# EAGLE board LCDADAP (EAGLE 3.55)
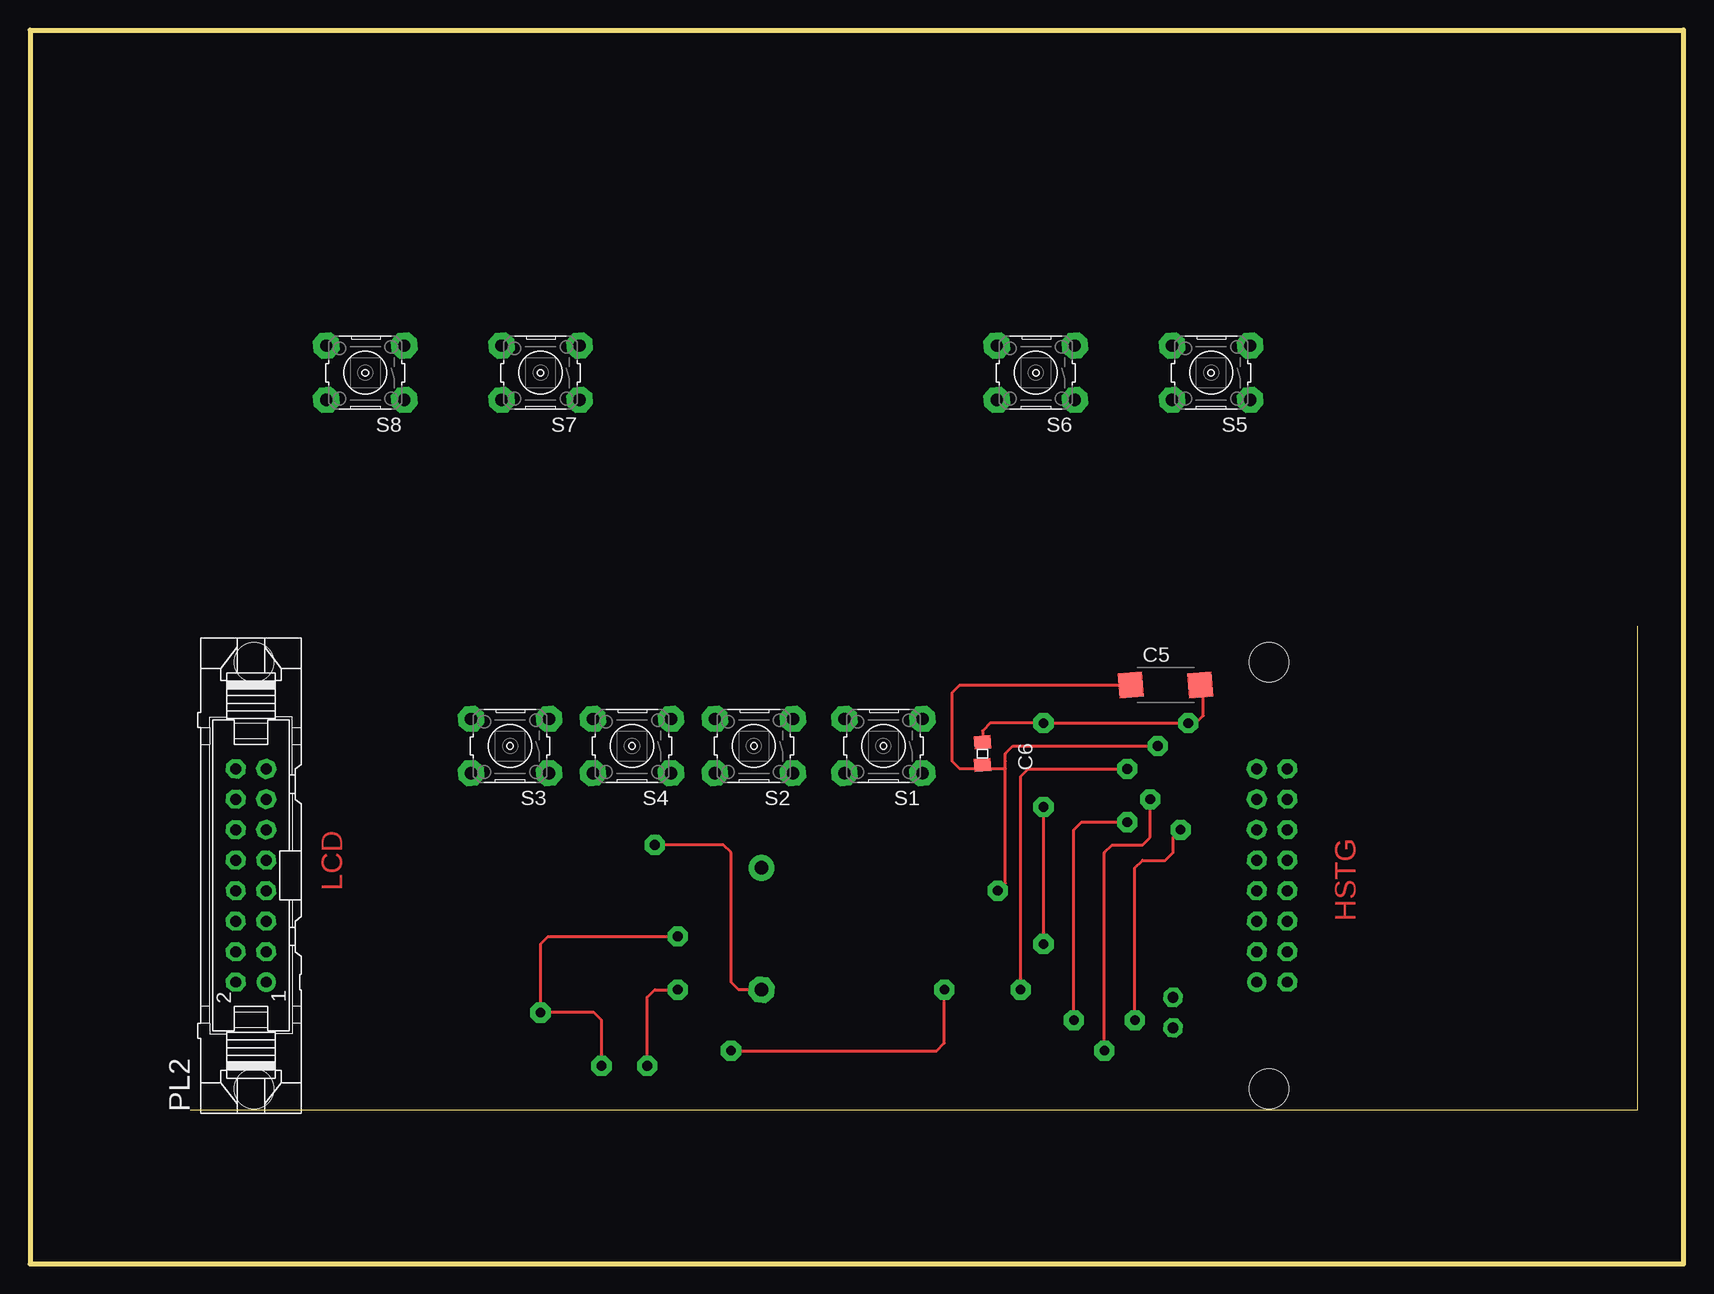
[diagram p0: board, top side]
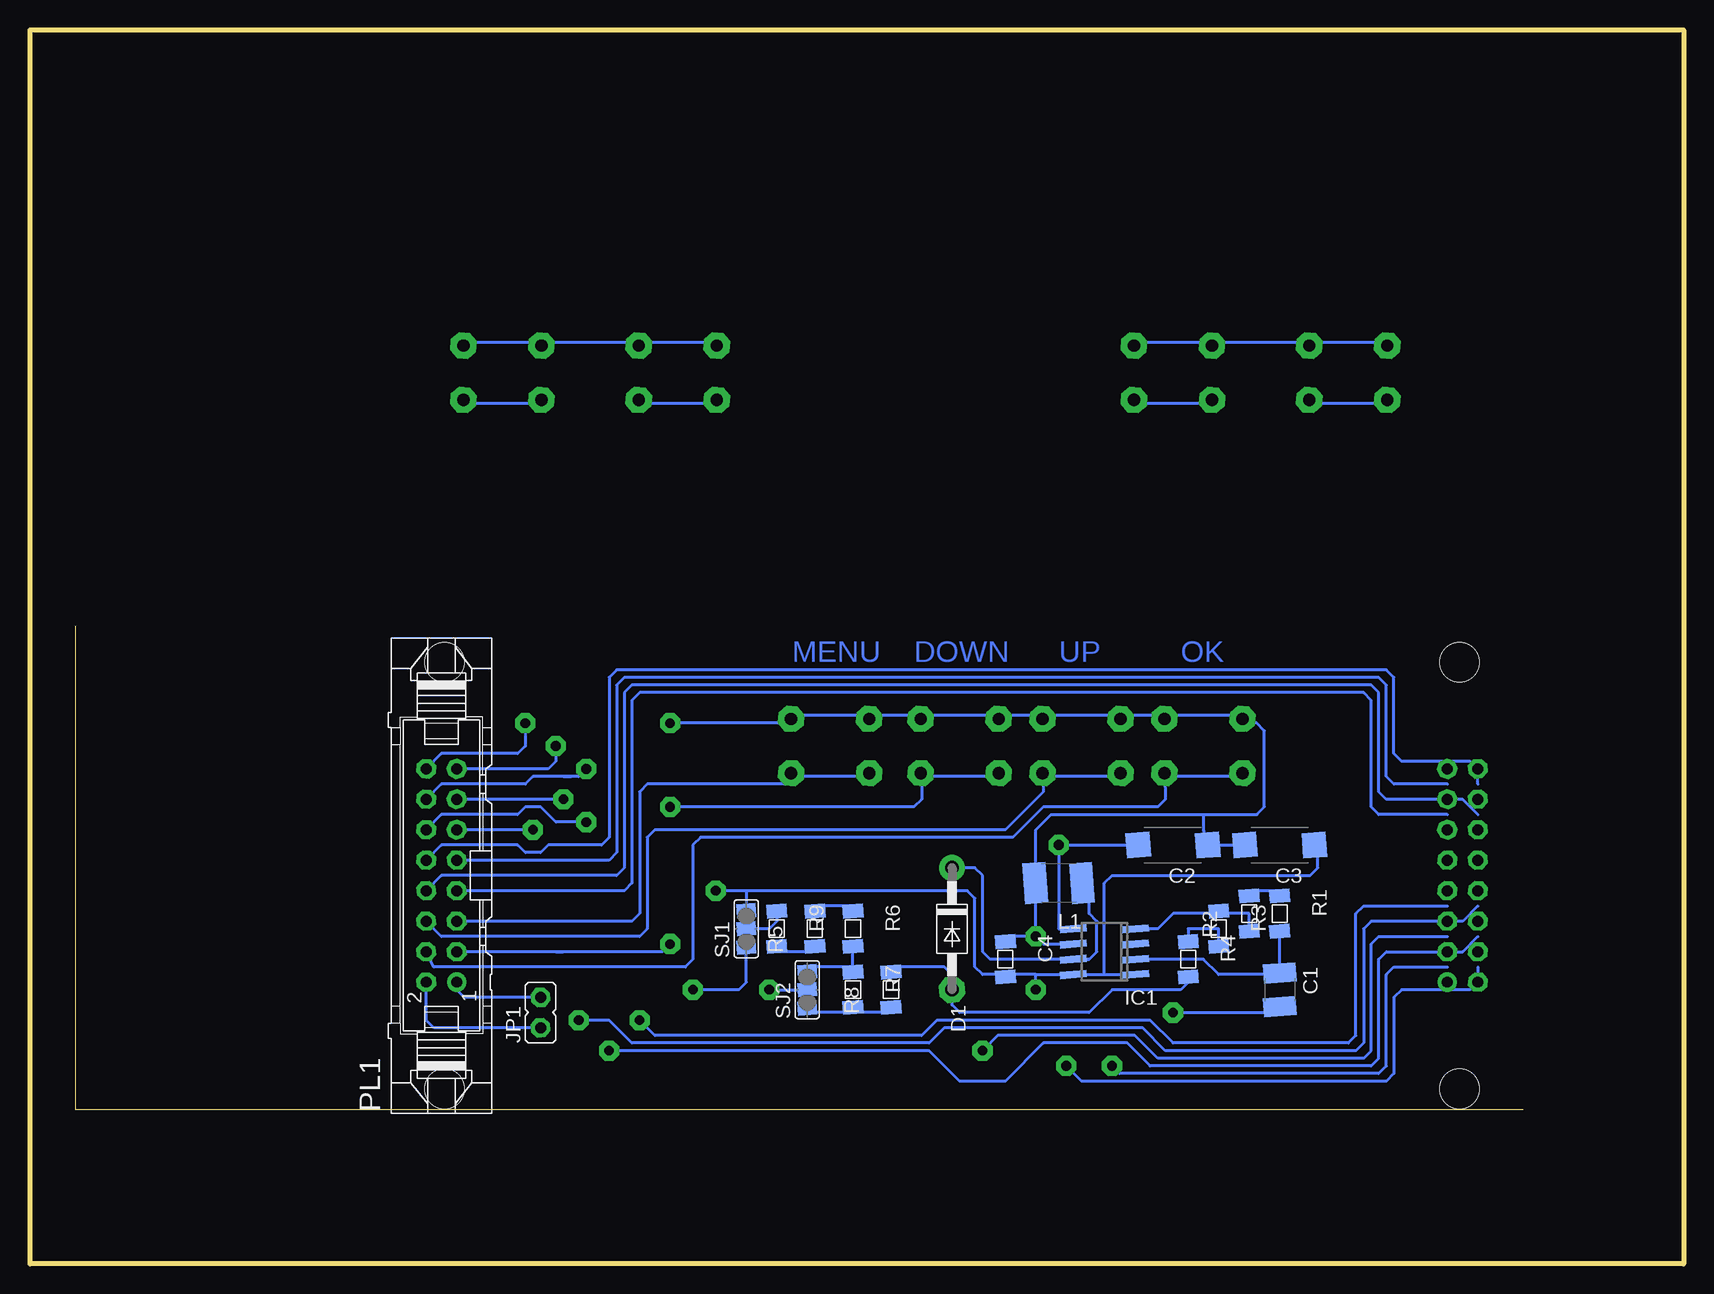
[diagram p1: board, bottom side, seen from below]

Size 137.79 x 102.87 mm. Coordinates in mm from the lower left corner, seen from the top.
Outline: 133.98,53.17 133.98,12.86 13.34,12.86
Outline: 0,0 137.79,0 137.79,102.87 0,102.87 0,0
Copper layers used: Top, Bottom
vRestrict: area 67.3,50.8 to 91.4,74.9

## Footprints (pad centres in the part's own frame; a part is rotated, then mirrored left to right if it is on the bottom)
210 = smd 1.6 x 2.7 rotated 4.3:  -1.4,0 | smd 1.6 x 2.7 rotated 4.4:  1.4,0
512W = smd 2 x 2.1 rotated 4.3:  -2.896,0 | smd 2 x 2.1 rotated 4.4:  2.896,0
06 = smd 1.143 x 1.702 rotated 4.4:  1.473,0 | smd 1.143 x 1.702 rotated 4.3:  -1.473,0
05 = smd 1.092 x 1.397 rotated 4.4:  0.94,0 | smd 1.092 x 1.397 rotated 4.3:  -0.94,0
41-10 = drill 1.118 pad 2.159 octagon:  5.08,0 | drill 1.118 pad 2.159 round:  -5.08,0
8 = smd 0.6 x 2.2 rotated 4.4:  -0.635,-2.6 | smd 0.6 x 2.2 rotated 4.8:  -0.635,2.6 | smd 0.6 x 2.2 rotated 4.3:  -1.905,-2.6 | smd 0.6 x 2.2 rotated 4.5:  0.635,-2.6 | smd 0.6 x 2.2 rotated 4.6:  1.905,-2.6 | smd 0.6 x 2.2 rotated 4.9:  -1.905,2.6 | smd 0.6 x 2.2 rotated 4.7:  0.635,2.6;  1.905,2.6
1 = drill 0.914 pad 1.6 octagon:  0,-1.27;  0,1.27
812 = smd 1.9 x 3.4 rotated 4.3:  -1.95,0 | smd 1.9 x 3.4 rotated 4.4:  1.95,0
V = drill 0.914 pad 1.6 round:  -8.89,-1.27 | drill 0.914 pad 1.6 octagon:  -8.89,1.27;  -6.35,-1.27;  -6.35,1.27;  -3.81,-1.27;  -3.81,1.27;  -1.27,-1.27;  -1.27,1.27;  1.27,-1.27;  1.27,1.27;  3.81,-1.27;  3.81,1.27;  6.35,-1.27;  6.35,1.27;  8.89,-1.27;  8.89,1.27 | hole 3.302: 17.78,-0.254; -17.78,-0.254
F-10XX = drill 1.016 pad 2.159 octagon:  -3.251,2.261;  -3.251,-2.261;  3.251,2.261;  3.251,-2.261
2 = smd 1.168 x 1.6 rotated 4.3:  -1.524,0 | smd 1.168 x 1.6 rotated 4.4:  0,0 | smd 1.168 x 1.6 rotated 4.5:  1.524,0

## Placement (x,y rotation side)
C1  10uF  [210]  33.66,22.86 270 bottom
C2  100uF  [512W]  42.55,34.92 180 bottom
C3  47uF  [512W]  33.66,34.92 180 bottom
C4  1uFceram  [06]  56.52,25.4 270 bottom
C5  100uF  [512W]  94.62,48.26 0 top
C6  100n  [05]  79.38,42.55 270 top
D1  1N5817  [41-10]  60.96,27.94 270 bottom
IC1  MAX755  [8]  48.26,26.04 90 bottom
JP1  JP1E  [1]  95.25,20.95 0 bottom
L1  10uH  [812]  52.07,31.75 180 bottom
PL1  16V  [V]  103.5,32.38 90 bottom
PL2  14V  [V]  18.41,32.38 90 top
R1  2k7  [06]  33.66,29.21 270 bottom
R2  10k  [06]  36.2,29.21 90 bottom
R3  47k  [06]  38.73,27.94 270 bottom
R4  4k7  [06]  41.28,25.4 270 bottom
R5  tbd  [06]  72.39,27.94 90 bottom
R6  tbd  [06]  69.22,27.94 270 bottom
R7  tbd  [06]  69.22,22.86 270 bottom
R8  tbd  [06]  66.04,22.86 90 bottom
R9  tbd  [06]  75.56,27.94 270 bottom
S1  MENU  [F-10XX]  71.12,43.18 180 top
S2  DOWN  [F-10XX]  60.33,43.18 180 top
S3  OK  [F-10XX]  40.01,43.18 180 top
S4  UP  [F-10XX]  50.16,43.18 180 top
S5  menu  [F-10XX]  98.43,74.3 180 top
S6  ok  [F-10XX]  83.82,74.3 180 top
S7  up  [F-10XX]  42.55,74.3 180 top
S8  down  [F-10XX]  27.94,74.3 180 top
SJ1  SJ2  [2]  78.1,27.94 90 bottom
SJ2  SJ2  [2]  73.03,22.86 90 bottom

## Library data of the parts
C1-C3 C5 L1 = ipc-rcl
C4 C6 R1-R9 = smd
D1 = diode
IC1 = andit4at
JP1 = jumps
PL1 PL2 = pinh-v
S1-S8 = keyomron
SJ1 SJ2 = jumper

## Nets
GND: C1. C2. C3. C4. C5. C6. IC1. L1. PL1. PL2. S1. S2. S3. S4.
N$1: IC1. R2. R3.
N$2: C3. C4. C5. C6. IC1. PL1. PL2. SJ1.
N$3: PL1. SJ1.
N$4: PL1. PL2.
N$5: PL1. PL2.
N$6: PL1. PL2.
N$7: PL1. PL2.
N$9: PL1. PL2.
N$10: PL1. PL2.
N$11: PL1. PL2.
N$12: PL1. S4.
N$13: PL1. S1.
N$15: PL1. S2.
N$16: PL1. S3.
N$17: JP1. PL1.
N$18: JP1. PL1.
N$19: PL2. SJ2.
N$20: C2. D1. IC1. R4. R8.
N$21: R1. R2.
N$22: R5. R6.
N$23: R6. R7. SJ2.
N$24: C1. IC1. R1.
N$25: R3. R4.
N$26: R7. R8. SJ2.
N$27: R9. SJ1.
N$28: D1. IC1. L1.
N$29: R5. R9.
N$30: S7. S8.
N$32: S8.
N$33: S7.
N$34: S5. S6.
N$36: S6.
N$37: S5.

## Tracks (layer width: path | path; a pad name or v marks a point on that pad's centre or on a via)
GND  (via drill 0.81 pad 1.68)
  Top 0.254: v47.62,16.51 47.62,20.32 46.99,20.95 v42.55,20.95 42.55,26.67 43.18,27.3 v53.98,27.3 | C6. 79.38,44.45 80.01,45.08 v84.46,45.08 v96.52,45.08 97.16,45.08 97.79,45.72 97.79,48.26 C5.
  Bottom 0.254: 19.69,24.77 24.13,24.77 24.77,24.13 24.77,16.51 25.4,15.88 46.99,15.88 v47.62,16.51 | PL1. 103.5,42.55 97.16,42.55 96.52,43.18 v96.52,45.08 | 40.01,37.47 40.01,36.2 39.65,34.92 C3. | 43.18,45.72 37.47,45.72 S3. 36.83,45.08 35.56,45.08 34.92,44.45 34.92,38.1 35.56,37.47 40.01,37.47 | 43.18,45.72 43.26,45.44 | 43.18,45.72 46.99,45.72 | 46.99,45.72 S4. | 46.99,45.72 53.34,45.72 | 53.34,45.72 53.42,45.44 | 53.34,45.72 57.15,45.72 | 57.15,45.72 S2. | 57.15,45.72 63.5,45.72 | 63.5,45.72 63.58,45.44 | 63.5,45.72 67.94,45.72 | 67.94,45.72 S1. | 67.94,45.72 74.3,45.72 | 74.3,45.72 74.37,45.44 | 74.3,45.72 74.93,45.08 v84.46,45.08 | 53.98,31.75 53.98,36.2 52.7,37.47 40.01,37.47 | 53.98,31.75 L1. | 50.86,26.67 53.34,26.67 v53.98,27.3 | v42.55,20.95 34.29,20.95 33.66,21.59 C1. | C4. 56.52,27.3 v53.98,27.3 | v53.98,27.3 53.98,31.75
N$1
  Bottom 0.254: 45.66,27.94 43.81,27.94 42.55,29.21 38.73,29.21 | R2. 36.2,29.21 38.73,29.21 | 38.73,29.21 R3.
N$2  (via drill 0.81 pad 1.68)
  Top 0.254: v51.44,16.51 51.44,22.23 52.07,22.86 v53.98,22.86 | v93.98,43.18 81.91,43.18 81.28,42.55 81.28,41.91 81.28,41.27 | v80.65,31.11 81.28,31.75 81.28,41.27 | 91.72,48.26 77.47,48.26 76.84,47.62 76.84,41.91 77.47,41.27 79.38,41.27 | 79.38,41.27 79.38,41.61 | 81.28,41.27 79.38,41.27
  Bottom 0.254: 17.14,24.77 17.14,23.49 17.78,22.86 23.5,22.86 24.13,22.23 24.13,15.88 24.77,15.24 50.16,15.24 v51.44,16.51 | 48.26,24.13 50.86,24.13 53.98,24.13 | 48.26,24.13 45.66,24.13 | 48.26,24.13 48.26,31.75 47.62,32.38 31.12,32.38 30.48,33.02 30.48,34.92 30.76,34.92 | 56.52,24.13 56.52,23.93 | 53.98,24.13 56.52,24.13 | v53.98,22.86 53.98,24.13 | 56.52,24.13 58.42,24.13 59.05,24.77 59.05,30.48 59.69,31.11 78.1,31.11 | 78.1,31.11 SJ1. | 102.24,41.27 94.62,41.27 93.98,41.91 v93.98,43.18 | 78.1,31.11 v80.65,31.11
N$3  (via drill 0.81 pad 1.68)
  Top 0.254: v91.44,41.27 83.19,41.27 82.55,40.64 v82.55,22.86
  Bottom 0.254: 104.78,38.73 103.5,40 96.52,40 95.88,40.64 93.34,40.64 | v91.44,41.27 92.07,40.64 93.34,40.64 | 93.34,40.64 92.71,40.64 | 78.1,26.42 78.1,23.49 78.74,22.86 v82.55,22.86
N$4  (via drill 0.81 pad 1.68)
  Top 0.254: v93.34,38.73 93.34,35.56 92.71,34.92 90.17,34.92 89.53,34.29 v89.53,17.78
  Bottom 0.254: 17.14,27.3 18.41,26.04 24.77,26.04 25.4,25.4 25.4,17.14 26.04,16.51 44.45,16.51 46.36,18.41 53.34,18.41 56.52,15.24 60.33,15.24 62.87,17.78 v89.53,17.78 | v93.34,38.73 102.24,38.73
N$5  (via drill 0.81 pad 1.68)
  Top 0.254: v91.44,36.83 87.63,36.83 87,36.2 v87,20.32
  Bottom 0.254: 19.69,29.84 26.67,29.84 27.3,29.21 27.3,19.05 27.94,18.41 42.55,18.41 44.45,20.32 62.23,20.32 63.5,19.05 85.72,19.05 v87,20.32 | 104.78,36.2 103.5,37.47 97.16,37.47 96.52,38.1 95.25,38.1 93.98,36.83 v91.44,36.83
N$6  (via drill 0.81 pad 1.68)
  Top 0.254: v95.88,36.2 95.25,35.56 95.25,34.29 94.62,33.66 92.71,33.66 92.07,33.02 v92.07,20.32
  Bottom 0.254: 17.14,29.84 18.41,28.57 26.04,28.57 26.67,27.94 26.67,18.41 27.3,17.78 43.18,17.78 45.09,19.68 61.59,19.68 62.87,18.41 87.63,18.41 89.53,20.32 v92.07,20.32 | v95.88,36.2 102.24,36.2
N$7
  Bottom 0.254: 17.14,40 PL2. 17.78,41.91 23.5,41.91 24.13,42.55 24.13,48.89 24.77,49.53 88.9,49.53 89.53,48.89 89.53,35.56 90.17,34.92 94.62,34.92 95.25,34.29 96.52,34.29 97.16,34.92 103.5,34.92 104.78,33.66
N$9
  Bottom 0.254: 19.69,40 24.13,40 24.77,40.64 24.77,48.26 25.4,48.89 88.27,48.89 88.9,48.26 88.9,34.29 89.53,33.66 102.24,33.66
N$10
  Bottom 0.254: 17.14,37.47 18.41,38.73 24.77,38.73 25.4,39.37 25.4,47.62 26.04,48.26 87.63,48.26 88.27,47.62 88.27,33.02 88.9,32.38 103.5,32.38 104.78,31.11
N$11
  Bottom 0.254: 19.69,37.47 25.4,37.47 26.04,38.1 26.04,46.99 26.67,47.62 87,47.62 87.63,46.99 87.63,31.75 88.27,31.11 102.24,31.11
N$12
  Bottom 0.254: 104.78,28.57 103.5,27.3 87,27.3 86.36,27.94 86.36,35.56 85.72,36.2 56.52,36.2 53.34,39.37 53.34,40.64 | 46.91,40.92 46.99,40.64 53.34,40.64 | 53.34,40.64 53.42,40.92
N$13
  Bottom 0.254: 67.87,40.92 67.94,40.64 74.3,40.64 | 74.3,40.64 74.37,40.92 | 74.3,40.64 74.93,40 86.36,40 87,39.37 87,29.21 87.63,28.57 102.24,28.57
N$15  (via drill 0.81 pad 1.68)
  Top 0.254: v84.46,38.1 v84.46,26.67
  Bottom 0.254: 57.07,40.92 57.15,40.64 63.5,40.64 | 63.5,40.64 63.58,40.92 | 63.5,40.64 63.5,38.73 64.13,38.1 v84.46,38.1 | 93.98,26.04 93.34,26.04 | 93.98,26.04 102.24,26.04 | 93.98,26.04 85.09,26.04 v84.46,26.67
N$16
  Bottom 0.254: 104.78,26.04 104.14,24.77 83.19,24.77 82.55,25.4 82.55,34.92 81.91,35.56 55.88,35.56 53.34,38.1 43.81,38.1 43.18,38.73 43.18,39.37 43.26,40.92 43.18,40.64 36.83,40.64 36.75,40.92
N$17
  Bottom 0.254: JP1. 101.6,22.23 102.24,22.86 102.24,23.49
N$18
  Bottom 0.254: 104.78,23.49 104.78,20.32 104.14,19.68 95.25,19.68
N$19  (via drill 0.81 pad 1.68)
  Top 0.254: v76.2,22.86 76.2,18.41 75.56,17.78 v58.42,17.78
  Bottom 0.254: 19.69,27.3 25.4,27.3 26.04,26.67 26.04,17.78 26.67,17.14 43.81,17.14 45.72,19.05 57.15,19.05 v58.42,17.78 | v76.2,22.86 73.03,22.86
N$20  (via drill 0.81 pad 1.68)
  Top 0.254: 60.96,22.86 59.05,22.86 58.42,23.49 58.42,34.29 57.79,34.92 v52.07,34.92
  Bottom 0.254: C2. v52.07,34.92 52.07,27.94 IC1. | 41.28,23.93 41.28,23.49 41.91,22.86 47.62,22.86 49.53,20.95 60.33,20.95 60.96,21.59 60.96,22.86 60.96,24.13 61.59,24.77 66.04,24.77 66.04,24.33
N$21
  Bottom 0.254: R1. 33.66,31.11 36.2,31.11 36.2,30.68
N$22
  Bottom 0.254: R6. 69.22,29.84 72.39,29.84 72.39,29.41
N$23
  Bottom 0.254: 69.22,24.13 R7. 69.22,24.77 | 69.22,24.77 69.22,26.47 | SJ2. 73.03,24.77 69.22,24.77
N$24
  Bottom 0.254: 33.66,27.74 33.66,24.26 33.66,24.13 38.73,24.13 40.01,25.4 45.66,25.4
N$25
  Bottom 0.254: 38.73,26.47 38.73,27.94 41.28,27.94 R4. 41.28,26.67
N$26
  Bottom 0.254: R8. 66.04,20.95 69.22,20.95 | 69.22,20.95 69.22,21.39 | 73.03,21.34 73.03,20.95 69.22,20.95
N$27
  Bottom 0.254: 75.56,29.84 R9. 75.56,28.57 76.2,27.94 78.1,27.94
N$28
  Bottom 0.254: 50.86,25.4 49.53,25.4 | 50.16,31.75 50.12,31.75 49.53,31.75 49.53,29.21 48.9,28.57 48.9,26.04 49.53,25.4 | 49.53,25.4 57.79,25.4 58.42,26.04 58.42,32.38 59.05,33.02 D1.
N$29
  Bottom 0.254: R5. 72.39,26.04 75.56,26.04 75.56,26.47
N$30
  Bottom 0.254: S8. 24.77,76.84 31.12,76.84 | 31.12,76.84 31.19,76.56 | 39.37,76.84 31.12,76.84 | 39.37,76.84 S7. | 45.8,76.56 45.72,76.84 39.37,76.84
N$32
  Bottom 0.254: 24.69,72.03 24.77,71.75 31.12,71.75 31.19,72.03
N$33
  Bottom 0.254: 39.29,72.03 39.37,71.75 45.72,71.75 45.8,72.03
N$34
  Bottom 0.254: S6. 80.65,76.84 87,76.84 | 87,76.84 87.07,76.56 | 95.25,76.84 87,76.84 | 95.25,76.84 S5. | 101.68,76.56 101.6,76.84 95.25,76.84
N$36
  Bottom 0.254: 80.57,72.03 80.65,71.75 87,71.75 87.07,72.03
N$37
  Bottom 0.254: 95.17,72.03 95.25,71.75 101.6,71.75 101.68,72.03

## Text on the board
Top: LCD | HSTG
Bottom: OK | UP | DOWN | MENU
